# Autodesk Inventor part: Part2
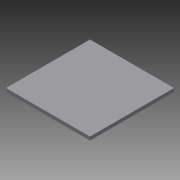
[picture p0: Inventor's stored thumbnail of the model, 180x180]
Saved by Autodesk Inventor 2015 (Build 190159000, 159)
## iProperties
Created: 2015-04
Part Number: Part2
Material: Generic
Document SubType Name: Modeling
Designer: TREINA5
Density: 1 g/cm^3
Appearance: Default
Mass: 131424 g
Surface Area: 47360 cm^2
Volume: 131424 cm^3
Author: TREINA5
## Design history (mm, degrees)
sketch "Sketch1"
  geometry: L1 (0, 10480)-(1480, 10480); L2 (1500, 10480)-(2980, 10480); L3 (0, 7480)-(1480, 7480); L4 (0, 8980.017)-(1480, 8980.017); L5 (0, 7500.017)-(0, 8980.017); L6 (0, 9000)-(1480, 9000); L7 (2980, 8980)-(2980, 7500); L8 (1500, 7500)-(2980, 7500); L9 (1500, 7480)-(2980, 7480); L10 (10500, 4480)-(11980, 4480); L11 (11980, 4480)-(11980, 3000); L12 (10500, 3000)-(10500, 4480); L13 (10500, 3000)-(11980, 3000); L14 (1500, 7480)-(2980, 7480); L15 (2980, 8980)-(2980, 7500); L16 (1500, 7500)-(2980, 7500); L17 (3000, 7500)-(3000, 8980); L18 (10500, 6000)-(10500, 7480); L19 (11940.002, 8980)-(11979.983, 8980); L20 (0, 7500.017)-(4.13, 7500.017); L21 (336.554, 7500.017)-(1480, 7500.017); L22 (1480, 8980.017)-(1480, 7897.684); L23 (1480, 7874.661)-(1480, 7500.017); L24 (1500, 7500)-(1500, 7886.157); L25 (1500, 7909.283)-(1500, 8980); L26 (1500, 7500)-(1500, 7886.157); L27 (1500, 7909.283)-(1500, 8980); L28 (1500, 8980)-(2570.717, 8980); L29 (2593.843, 8980)-(2980, 8980); L30 (1500, 8980)-(2570.717, 8980); L31 (2593.843, 8980)-(2980, 8980); L32 (1500, 9000)-(2582.316, 9000); L33 (2605.339, 9000)-(2980, 9000); L34 (1500, 9000)-(2582.316, 9000); L35 (2605.339, 9000)-(2980, 9000); L36 (2980, 10143.59)-(2980, 9000); L37 (2980, 10143.59)-(2980, 9000); L38 (10500, 8980)-(10740.282, 8980); L39 (10701.515, 8980)-(11940.002, 8980); L40 (10500, 4499.966)-(11480.132, 4499.966); L41 (11500.034, 4499.966)-(11980, 4499.966); L42 (10500, 2980)-(11480.131, 2980); L43 (11500.033, 2980)-(11980, 2980); L44 (0, 9000)-(0, 10480); L45 (1480, 10480)-(1480, 9000); L46 (1500, 9000)-(1500, 10480); L47 (14.142, 10480)-(1480, 10480); L48 (1500, 10480)-(2980, 10480); L49 (11979.983, 5999.198)-(10499.983, 5999.198); L50 (10499.983, 7479.198)-(10499.983, 5999.198); L51 (11979.983, 5999.198)-(10499.983, 5999.198); L52 (10499.983, 7479.198)-(10499.983, 5999.198); L53 (10500, 8642.5)-(10500, 7499.198); L54 (13149.912, 5999.198)-(11999.983, 5999.198); L55 (13149.912, 5999.198)-(11999.983, 5999.198); L56 (10500, 7499.198)-(10874.958, 7499.198); L57 (10898.159, 7499.198)-(11979.983, 7499.198); L58 (10500, 7479.198)-(10886.462, 7479.198); L59 (10909.766, 7479.198)-(11979.983, 7479.198); L60 (12000, 7479.198)-(13479.814, 7479.198); L61 (13479.814, 7479.198)-(13479.998, 6000.083); L62 (11979.983, 5999.198)-(11979.983, 6386.041); L63 (11979.983, 6409.341)-(11979.983, 7479.198); L64 (11979.983, 7499.198)-(11979.983, 8980)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; A1 r 1510 centre (11990, 2990.034) between (10480.034, 3000.067) and (10480.033, 2999.966); A2 r 1510 centre (11990, 4489.966) between (10480.034, 4479.966) and (10480.034, 4479.933); A3 r 3010.067 centre (13489.917, 8990) between (10500, 8642.293) and (10874.958, 7499.198); A4 r 3010.067 centre (13489.917, 8990) between (10886.462, 7479.198) and (11979.983, 6386.041); A5 r 3010.067 centre (13489.917, 8990) between (12000, 6374.536) and (13149.912, 5999.198); A6 r 2989.933 centre (13489.917, 8990) between (12000, 6397.733) and (13479.998, 6000.083); A7 r 2989.933 centre (13489.917, 8990) between (10500, 8980) and (10898.159, 7499.198); A8 r 2989.933 centre (13489.917, 8990) between (10909.766, 7479.198) and (11979.983, 6409.341); A9 r 3010 centre (-10, 10490) between (336.554, 7500.017) and (1500, 7886.157); A10 r 3010 centre (-10, 10490) between (1500, 7886.157) and (2593.843, 8980); A11 r 3010 centre (-10, 10490) between (2605.339, 9000) and (2980, 10143.59); A12 r 2990 centre (-10, 10490) between (2582.296, 9000) and (2979.983, 10480); A13 r 2990 centre (-10, 10490) between (-19.983, 7500.017) and (1500, 7909.302); A14 r 2990 centre (-10, 10490) between (-0.017, 7500.017) and (1480, 7897.704); A15 r 2990 centre (-10, 10490) between (1500, 7909.302) and (2570.698, 8980); 1 further point
  constraints: 134 end point, 33 point on circle, 16 point on line, 15 centre point, 1 other
extrude "Extrusion1" new body sketch "Sketch1" distance "d0" = 60; taper "d1" = 0 deg
body "Solid1"
